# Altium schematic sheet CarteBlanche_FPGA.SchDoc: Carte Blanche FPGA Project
size A1; DrawnBy: SRKH; Engineer: SRKH; DocumentNumber: 1; Revision: CB500E; SheetNumber: 1; SheetTotal: 1
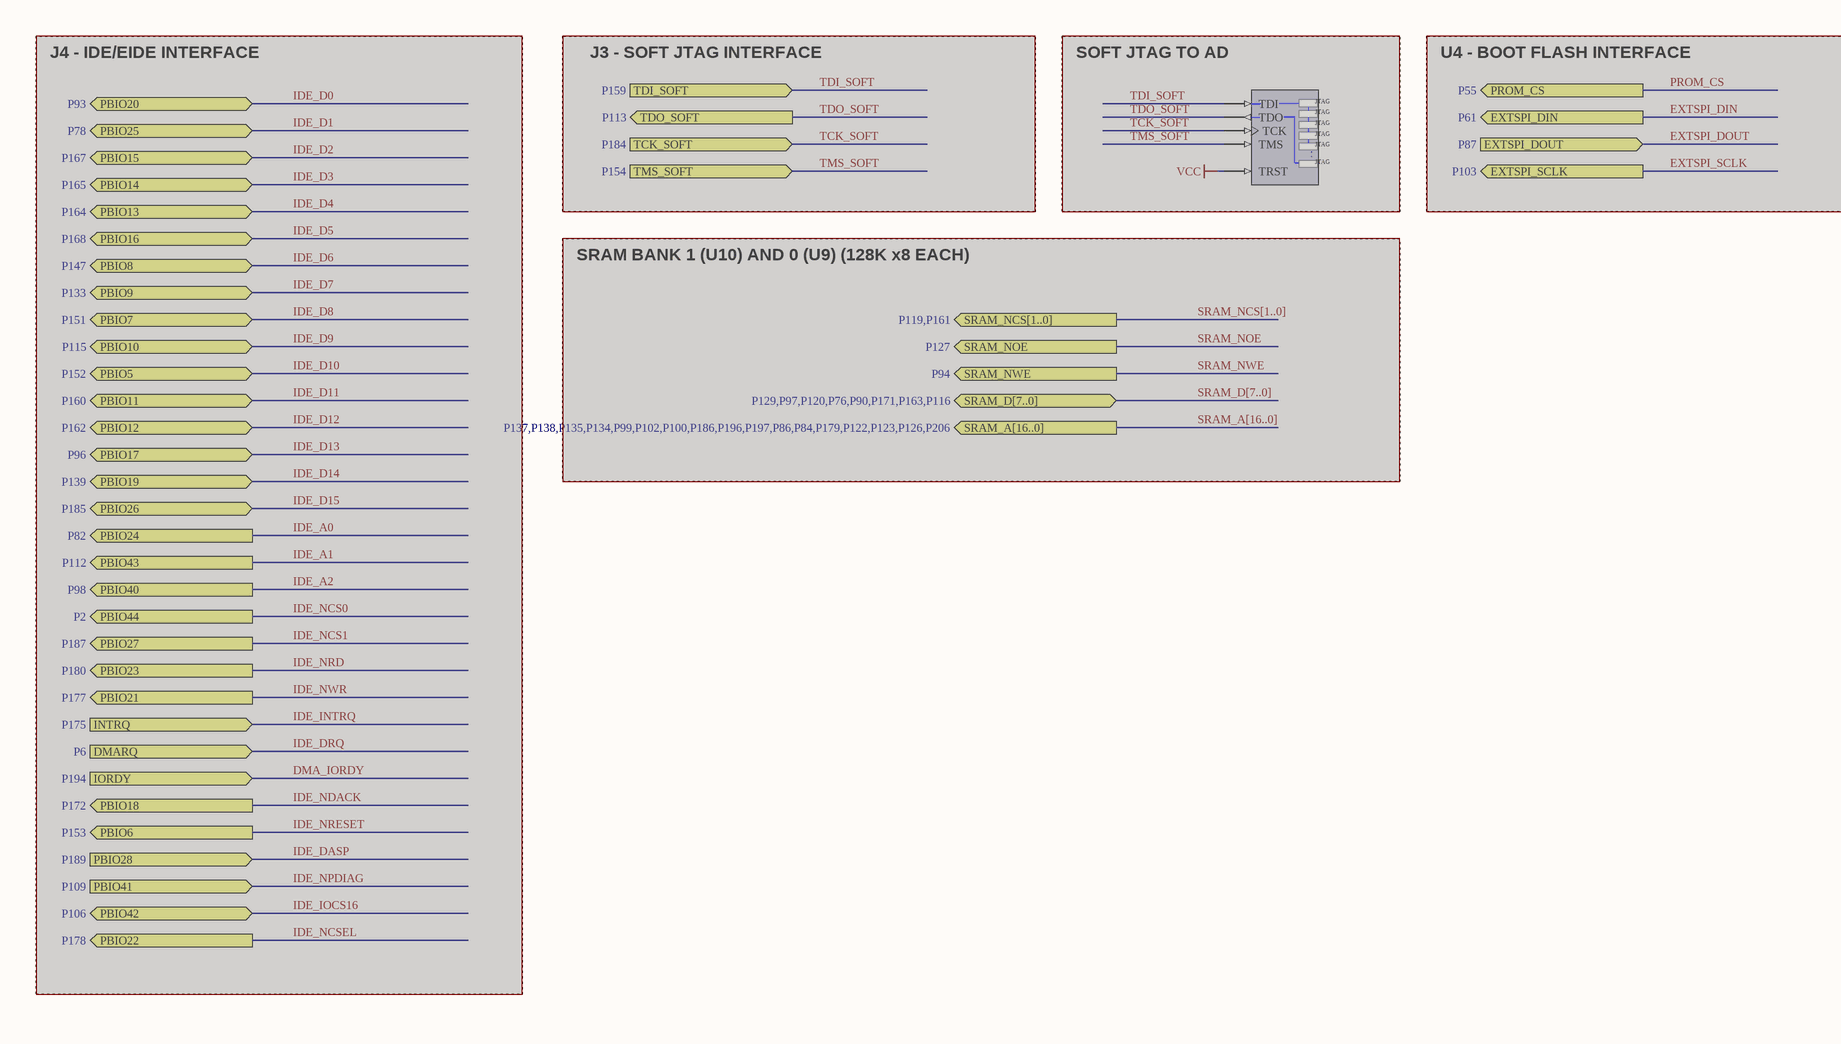
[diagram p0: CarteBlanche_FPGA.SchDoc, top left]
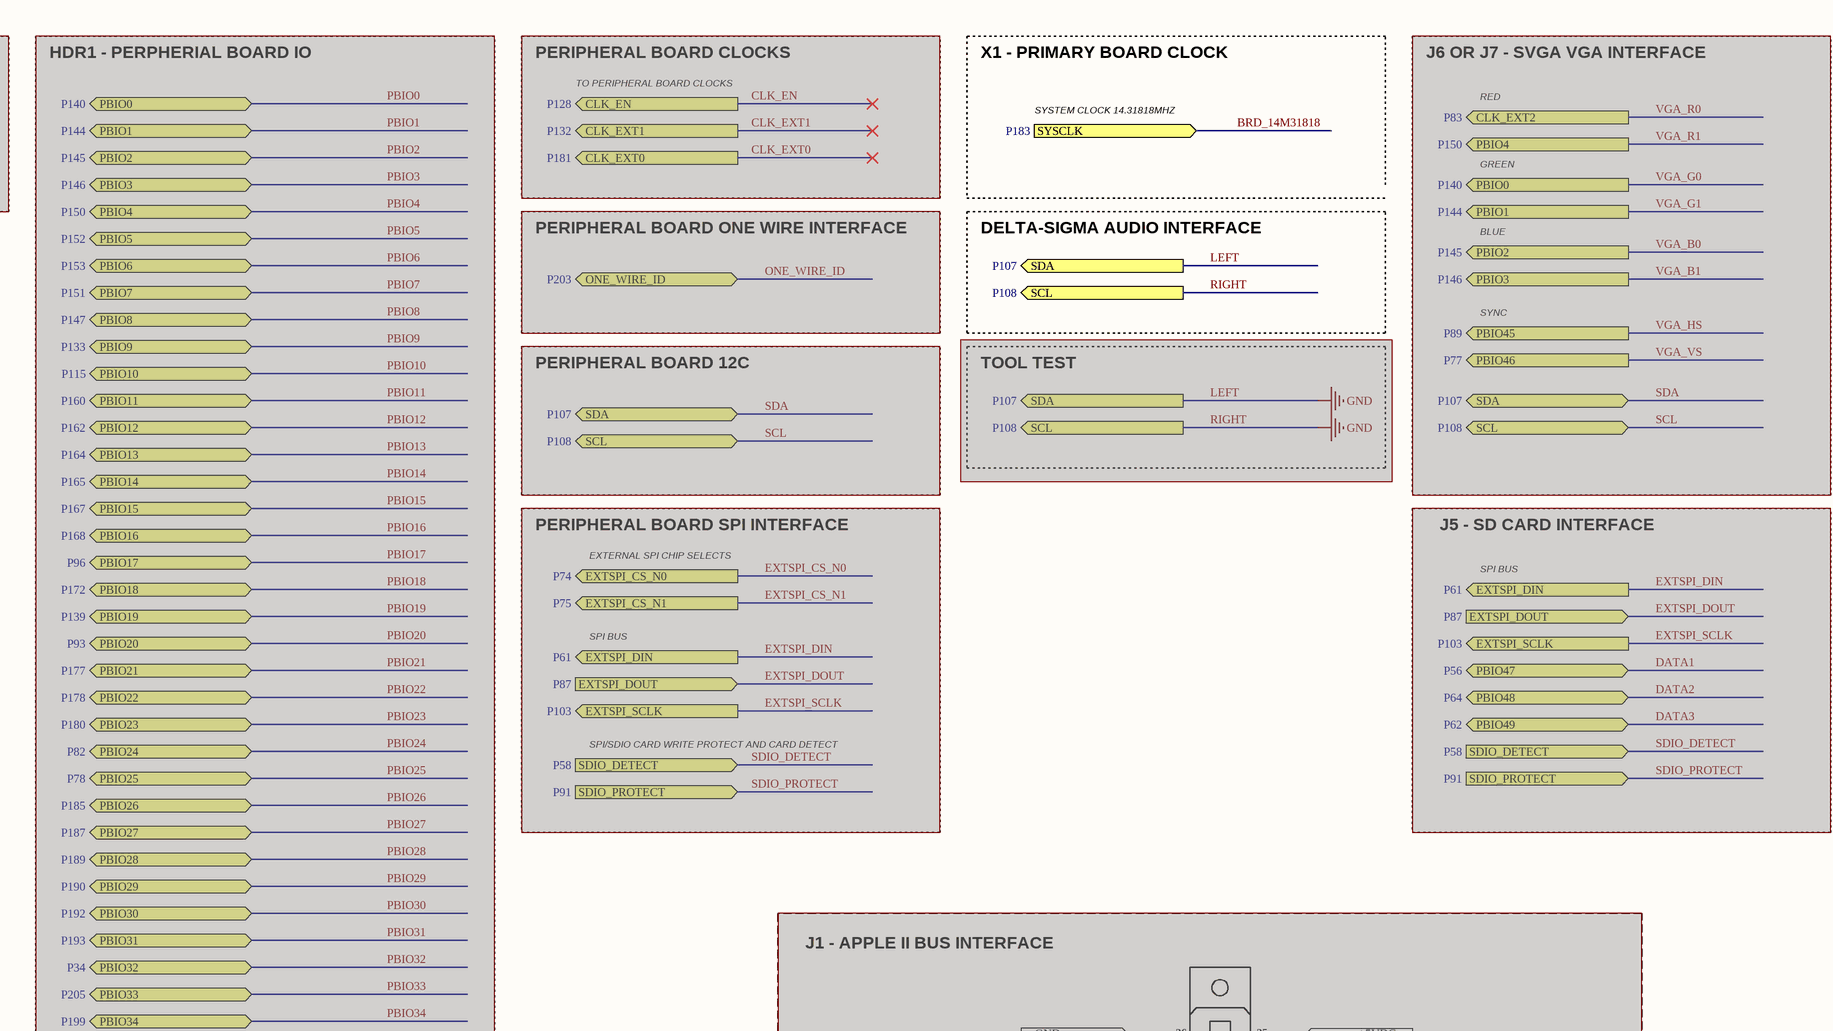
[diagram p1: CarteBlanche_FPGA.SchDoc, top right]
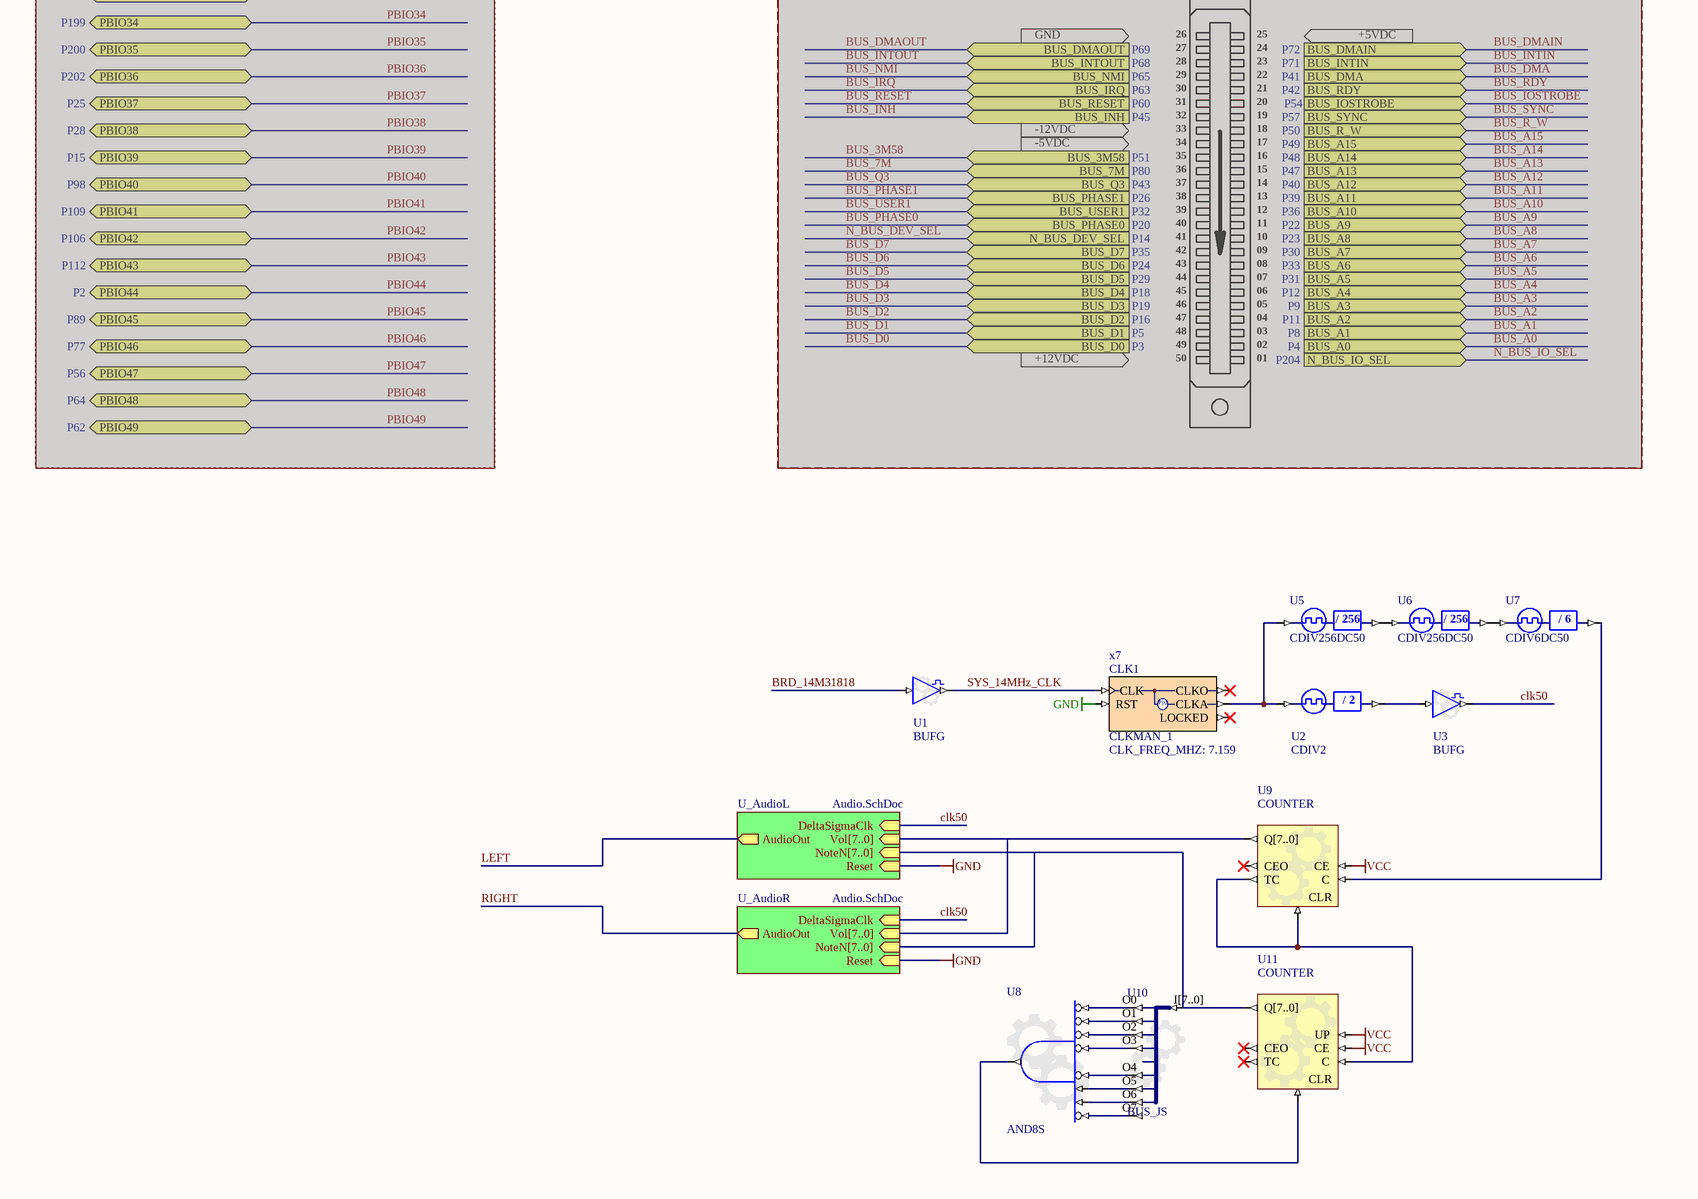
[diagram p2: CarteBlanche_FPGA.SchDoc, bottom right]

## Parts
CLK1  CLKMAN_1  CLK_FREQ_MHZ: 7.159  ClkA_Operation: x7
NEXUS_JTAG_PORT  NEXUS_JTAG_PORT  (value not drawn)  (masked out: inside a compile mask, not in the netlist)
U1  BUFG
U2  CDIV2
U3  BUFG
U5  CDIV256DC50
U6  CDIV256DC50
U7  CDIV6DC50
U8  AND8S
U9  COUNTER
U10  BUS_JS
U11  COUNTER

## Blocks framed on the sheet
SOFT JTAG TO AD: NEXUS_JTAG_PORT

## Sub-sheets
U_AudioL = Audio.SchDoc: AudioOut (out), DeltaSigmaClk (in), Reset (in), NoteN[7..0] (in), Vol[7..0] (in)
U_AudioR = Audio.SchDoc: AudioOut (out), DeltaSigmaClk (in), Reset (in), NoteN[7..0] (in), Vol[7..0] (in)

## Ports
BUS_3M58 (in, see P51), BUS_7M (in, see P80), BUS_A0 (in, see P4), BUS_A1 (in, see P8), BUS_A2 (in, see P11), BUS_A3 (in, see P9), BUS_A4 (in, see P12), BUS_A5 (in, see P31), BUS_A6 (in, see P33), BUS_A7 (in, see P30), BUS_A8 (in, see P23), BUS_A9 (in, see P22), BUS_A10 (in, see P36), BUS_A11 (in, see P39), BUS_A12 (in, see P40), BUS_A13 (in, see P47), BUS_A14 (in, see P48), BUS_A15 (in, see P49), BUS_D0 (in, see P3), BUS_D1 (in, see P5), BUS_D2 (in, see P16), BUS_D3 (in, see P19), BUS_D4 (in, see P18), BUS_D5 (in, see P29), BUS_D6 (in, see P24), BUS_D7 (in, see P35), BUS_DMA (in, see P41), BUS_DMAIN (in, see P72), BUS_DMAOUT (in, see P69), BUS_INH (in, see P45), BUS_INTIN (in, see P71), BUS_INTOUT (in, see P68), BUS_IOSTROBE (in, see P54), BUS_IRQ (in, see P63), BUS_NMI (in, see P65), BUS_PHASE0 (in, see P20), BUS_PHASE1 (in, see P26), BUS_Q3 (in, see P43), BUS_R_W (in, see P50), BUS_RDY (in, see P42), BUS_RESET (in, see P60), BUS_SYNC (in, see P57), BUS_USER1 (in, see P32), CLK_EN (out, see P128), CLK_EXT0 (out, see P181), CLK_EXT1 (out, see P132), CLK_EXT2 (out, see P83), DMARQ (in, see P6), EXTSPI_CS_N0 (out, see P74), EXTSPI_CS_N1 (out, see P75), EXTSPI_DIN (out, see P61), EXTSPI_DOUT (in, see P87), EXTSPI_SCLK (out, see P103), INTRQ (in, see P175), IORDY (in, see P194), N_BUS_DEV_SEL (in, see P14), N_BUS_IO_SEL (in, see P204), ONE_WIRE_ID (bidir, see P203), PBIO0 (bidir, see P140), PBIO0 (out, see P140), PBIO1 (bidir, see P144), PBIO1 (out, see P144), PBIO2 (bidir, see P145), PBIO2 (out, see P145), PBIO3 (bidir, see P146), PBIO3 (out, see P146), PBIO4 (bidir, see P150), PBIO4 (out, see P150), PBIO5 (bidir, see P152), PBIO6 (bidir, see P153), PBIO6 (out, see P153), PBIO7 (bidir, see P151), PBIO8 (bidir, see P147), PBIO9 (bidir, see P133), PBIO10 (bidir, see P115), PBIO11 (bidir, see P160), PBIO12 (bidir, see P162), PBIO13 (bidir, see P164), PBIO14 (bidir, see P165), PBIO15 (bidir, see P167), PBIO16 (bidir, see P168), PBIO17 (bidir, see P96), PBIO18 (bidir, see P172), PBIO18 (out, see P172), PBIO19 (bidir, see P139), PBIO20 (bidir, see P93), PBIO21 (bidir, see P177), PBIO21 (out, see P177), PBIO22 (bidir, see P178), PBIO22 (out, see P178), PBIO23 (bidir, see P180), PBIO23 (out, see P180), PBIO24 (bidir, see P82), PBIO24 (out, see P82), PBIO25 (bidir, see P78), PBIO26 (bidir, see P185), PBIO27 (bidir, see P187), PBIO27 (out, see P187), PBIO28 (bidir, see P189), PBIO28 (in, see P189), PBIO29 (bidir, see P190), PBIO30 (bidir, see P192), PBIO31 (bidir, see P193), PBIO32 (bidir, see P34), PBIO33 (bidir, see P205), PBIO34 (bidir, see P199), PBIO35 (bidir, see P200), PBIO36 (bidir, see P202), PBIO37 (bidir, see P25), PBIO38 (bidir, see P28), PBIO39 (bidir, see P15), PBIO40 (bidir, see P98), PBIO40 (out, see P98), PBIO41 (bidir, see P109), PBIO41 (in, see P109), PBIO42 (bidir, see P106), PBIO43 (bidir, see P112), PBIO43 (out, see P112), PBIO44 (bidir, see P2), PBIO44 (out, see P2), PBIO45 (bidir, see P89), PBIO45 (out, see P89), PBIO46 (bidir, see P77), PBIO46 (out, see P77), PBIO47 (bidir, see P56), PBIO48 (bidir, see P64), PBIO49 (bidir, see P62), PROM_CS (out, see P55), SCL (bidir, see P108), SCL (out, see P108), SDA (bidir, see P107), SDA (out, see P107), SDIO_DETECT (in, see P58), SDIO_PROTECT (in, see P91), SRAM_A[16..0] (out, see P137,P138,P135,P134,P99,P102,P100,P186,P196,P197,P86,P84,P179,P122,P123,P126,P206), SRAM_D[7..0] (bidir, see P129,P97,P120,P76,P90,P171,P163,P116), SRAM_NCS[1..0] (out, see P119,P161), SRAM_NOE (out, see P127), SRAM_NWE (out, see P94), SYSCLK (in, see P183), TCK_SOFT (in, see P184), TDI_SOFT (in, see P159), TDO_SOFT (out, see P113), TMS_SOFT (in, see P154)

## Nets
GND: CLK1.RST ; sheet U_AudioL/Reset, sheet U_AudioR/Reset
VCC: U9.CE U11.CE U11.UP
BRD_14M31818: U1.I ; port SYSCLK
clk50: U3.O ; sheet U_AudioL/DeltaSigmaClk, sheet U_AudioR/DeltaSigmaClk
LEFT: port SDA, sheet U_AudioL/AudioOut
RIGHT: port SCL, sheet U_AudioR/AudioOut
SYS_14MHz_CLK: CLK1.CLK U1.O
NetCLK1_CLKA: CLK1.CLKA U2.CLKIN U5.CLKIN
NetU2_CLKDV: U2.CLKDV U3.I
NetU5_CLKDV: U5.CLKDV U6.CLKIN
NetU6_CLKDV: U6.CLKDV U7.CLKIN
NetU7_CLKDV: U7.CLKDV U9.C
NetU8_I0: U8.I0 U10.O7
NetU8_I1: U8.I1 U10.O6
NetU8_I2: U8.I2 U10.O5
NetU8_I3: U8.I3 U10.O4
NetU8_I4: U8.I4 U10.O3
NetU8_I5: U8.I5 U10.O2
NetU8_I6: U8.I6 U10.O1
NetU8_I7: U8.I7 U10.O0
NetU8_O: U8.O U11.CLR
NetU9_CLR: U9.CLR U9.TC U11.C

Not connected (* = marked no-connect by the designer): CLK1 CLKO* LOCKED*; U9 CEO* Q[7..0]; U10 I[7..0]; U11 CEO* Q[7..0] TC*

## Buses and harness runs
bus sheet U_AudioL/NoteN[7..0] = sheet U_AudioR/NoteN[7..0]
bus sheet U_AudioL/Vol[7..0] = sheet U_AudioR/Vol[7..0]

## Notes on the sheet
- J4 - IDE/EIDE INTERFACE
- J3 - SOFT JTAG INTERFACE
- U4 - BOOT FLASH INTERFACE
- HDR1 - PERPHERIAL BOARD IO
- PERIPHERAL BOARD CLOCKS
- X1 - PRIMARY BOARD CLOCK
- J6 OR J7 - SVGA VGA INTERFACE
- TO PERIPHERAL BOARD CLOCKS
- SYSTEM CLOCK 14.31818MHZ
- RED
- GREEN
- SRAM BANK 1 (U10) AND 0 (U9) (128K x8 EACH)
- PERIPHERAL BOARD ONE WIRE INTERFACE
- DELTA-SIGMA AUDIO INTERFACE
- BLUE
- SYNC
- PERIPHERAL BOARD 12C
- TOOL TEST
- PERIPHERAL BOARD SPI INTERFACE
- J5 - SD CARD INTERFACE
- EXTERNAL SPI CHIP SELECTS
- SPI BUS
- SPI/SDIO CARD WRITE PROTECT AND CARD DETECT
- J1 - APPLE II BUS INTERFACE
- GND
- 26
- 27
- 28
- 29
- 25
- 24
- 23
- 22
- +5VDC
- -12VDC
- 30
- 31
- 32
- 33
- 34
- 21
- 20
- 19
- 18
- 17
- -5VDC
- 35
- 36
- 37
- 38
- 39
- 16
- 15
- 14
- 13
- 12
- 40
- 41
- 42
- 43
- 44
- 11
- 10
- 09
- 08
- 07
- 45
- 46
- 47
- 48
- 49
- 06
- 05
- 04
- 03
- 02
- +12VDC
- 50
- 01

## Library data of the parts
CLK1 = CLKMAN_1: Single Operational Output Clock Manager; Clk_Count: 1
NEXUS_JTAG_PORT = NEXUS_JTAG_PORT: Soft Nexus-Chain Connector; NEXUS_JTAG_CONNECTOR: True
U1 U3 = BUFG: Configurable Global Clock Buffer; ConfiguratorName: GENERIC_BUFFER; ConfigurationParameters: {}Version[1.1]{}SignalCount[1]{}SignalWidth0[1]{}OutputOption0[Global Clock]{}EnableMode[None]{}ShowPinNames[False]{}
U2 = CDIV2: Clock Divider by 2; DivisorRate: 2; ArchiveName: GENERIC; VHDLIB_SIM: GENERIC_LIB
U5 U6 = CDIV256DC50: Clock Divider by 256 with 50% Duty Cycle Output; DivisorRate: 256; ArchiveName: GENERIC; VHDLIB_SIM: GENERIC_LIB; DutyCycle: 50
U7 = CDIV6DC50: Clock Divider by 6 with 50% Duty Cycle Output; DivisorRate: 6; ArchiveName: GENERIC; VHDLIB_SIM: GENERIC_LIB; DutyCycle: 50; XilinxEquivalent: CLK_DIV6
U8 = GATE: Configurable Generic Gate; ConfiguratorName: GENERIC_GATE; ConfigurationParameters: {}Version[1.1]{}GateKind[AND]{}BusInput[False]{}GateInputType[Bit]{}GateOutputOption[Normal]{}BusWidth[8]{}RegisterOutputs[False]{}NegativeClockEdge[False]{}InputCount[8]{}InputInvert0[True]{}InputInvert1[False]{}InputInvert2[False]{}InputInvert3[True]{}InputInvert4[True]{}InputInvert5[True]{}InputInvert6[True]{}InputInvert7[True]{}
U9 = COUNTER: Configurable Counter; ConfiguratorName: GENERIC_COUNTER; ConfigurationParameters: {}Version[1.0]{}Type[Binary]{}SyncReset[False]{}NegativeClockEdge[False]{}FixedDirection[True]{}IsIncrement[False]{}SignalWidth[8]{}MaxValue[255]{}BusOutput[True]{}Loadable[False]{}BusInput[False]{}ShowPinNames[True]{}
U10 = BUS_JS: Configurable Bus Joiner/Splitter; ConfiguratorName: GENERIC_BUS_JS; ConfigurationParameters: {}Version[1.1]{}SplitterJoinerType[Splitter]{}SignalCount[8]{}SignalWidth0[1]{}GapBelow0[1000000]{}ConnectionType0[Pin]{}SignalWidth1[1]{}GapBelow1[1000000]{}ConnectionType1[Pin]{}SignalWidth2[1]{}GapBelow2[1000000]{}ConnectionType2[Pin]{}SignalWidth3[1]{}GapBelow3[1000000]{}ConnectionType3[Pin]{}SignalWidth4[1]{}GapBelow4[1000000]{}ConnectionType4[Pin]{}SignalWidth5[1]{}GapBelow5[1000000]{}ConnectionType5[Pin]{}SignalWidth6[1]{}GapBelow6[1000000]{}ConnectionType6[Pin]{}SignalWidth7[1]{}GapBelow7[1000000]{}ConnectionType7[Pin]{}ShowPinNames[True]{}
U11 = COUNTER: Configurable Counter; ConfiguratorName: GENERIC_COUNTER; ConfigurationParameters: {}Version[1.0]{}Type[Binary]{}SyncReset[False]{}NegativeClockEdge[False]{}FixedDirection[False]{}IsIncrement[False]{}SignalWidth[8]{}MaxValue[255]{}BusOutput[True]{}Loadable[False]{}BusInput[False]{}ShowPinNames[True]{}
